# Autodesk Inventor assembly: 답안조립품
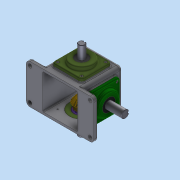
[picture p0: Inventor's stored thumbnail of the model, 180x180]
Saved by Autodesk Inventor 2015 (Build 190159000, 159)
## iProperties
Created: 2018-09
Part Number: 답안조립품
Document SubType Name: Assembly
Designer: SCD-A04
Author: SCD-A04
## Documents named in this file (15)
- C:\Users\SCD-A04\Desktop\380907V1018\답안조립품.iam
- C:\Users\SCD-A04\Desktop\380907V1018\본체.ipt
- C:\Users\SCD-A04\Desktop\380907V1018\상부커버.ipt
- C:\Users\SCD-A04\Desktop\380907V1018\서브커버.ipt
- C:\Users\SCD-A04\Desktop\380907V1018\메인커버.ipt
- C:\Users\SCD-A04\Desktop\380907V1018\베어링 6203.ipt
- C:\Users\SCD-A04\Desktop\380907V1018\베어링 6204.ipt
- C:\Users\SCD-A04\Desktop\380907V1018\오일 실 17 32 8.ipt
- C:\Users\SCD-A04\Desktop\380907V1018\오일 실 20 35 8.ipt
- C:\Users\SCD-A04\Desktop\380907V1018\서브축.ipt
- C:\Users\SCD-A04\Desktop\380907V1018\메인축.ipt
- C:\Users\SCD-A04\Desktop\380907V1018\볼트 M4.ipt
- C:\Users\SCD-A04\Desktop\380907V1018\키 4x4.ipt
- C:\Users\SCD-A04\Desktop\380907V1018\서브베벨기어.ipt
- C:\Users\SCD-A04\Desktop\380907V1018\메인베벨기어.ipt
